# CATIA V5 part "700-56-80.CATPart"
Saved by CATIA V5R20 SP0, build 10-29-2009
Part number: 700-56-80
Revision: ANY
Definition: UNKNOWN
Nomenclature: 700-56-80
Source: Unknown
Bounding box of the stored display mesh (mm): x -28 to 28, y 0 to 80, z -28 to 28
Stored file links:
  C:\Users\Utente\Desktop\IO LAVORO\3D X SITO CF\X SITO\700\700-56-80.CATPart
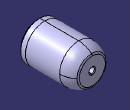
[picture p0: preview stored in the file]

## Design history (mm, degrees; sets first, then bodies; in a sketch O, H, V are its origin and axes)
Body1 "Rivoluzione1" (main body)
  Solid1: solid without history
